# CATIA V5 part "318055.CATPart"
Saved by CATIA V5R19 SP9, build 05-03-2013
Part number: 318055
Source: Unknown
Bounding box of the stored display mesh (mm): x -692.228 to 122.767, y -247.287 to -88.111, z 189.403 to 590.351
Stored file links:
  D:\16-SIL\kale oto\R19_V2\318055.CATPart
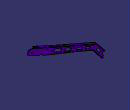
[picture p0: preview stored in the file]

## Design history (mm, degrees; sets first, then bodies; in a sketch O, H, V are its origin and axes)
Body1 "157\\125\\MANIFOLD_SOLID_BREP #78028" (main body)
  Solid1: solid without history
